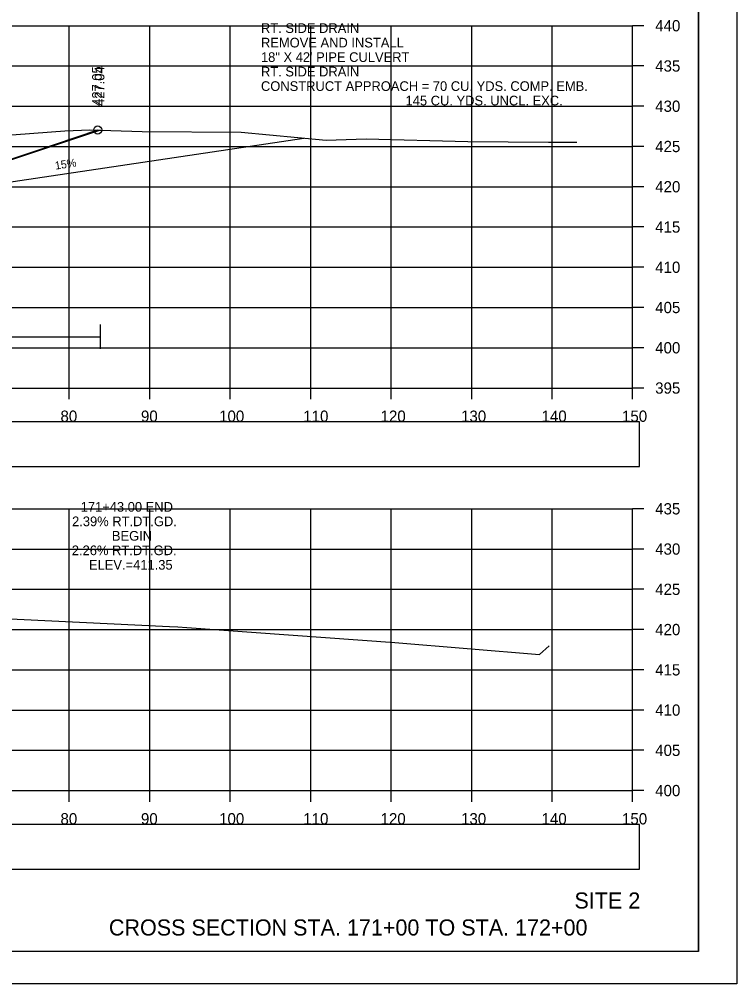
# Model space of a CAD drawing. Extents: x 1376273 to 1384221, y 378927 to 384592.
# Drawn here: x 1378664.4 to 1378753.6, y 381391.9 to 381511.6 of the extents above; entities that cross this region are included whole.
import ezdxf

# ---------------------------------------------------------------- set-up
doc = ezdxf.new("R2010")
doc.units = 0
for name, color, linetype in [('R_Axis', 7, 'Continuous'), ('R_Axis Annot', 7, 'Continuous'), ('R_Border', 7, 'Continuous'), ('R_Contours', 7, 'Continuous'), ('R_Dimension', 7, 'Continuous'), ('R_Draft', 7, 'Continuous'), ('R_Drive', 7, 'Continuous'), ('R_Exist Surface', 7, 'Continuous'), ('R_Fin Surface', 7, 'Continuous'), ('R_Grid', 7, 'Continuous'), ('R_No Plot', 7, 'Continuous'), ('R_Xsect Elev', 7, 'Continuous')]:
    doc.layers.add(name, color=color, linetype=linetype)

msp = doc.modelspace()

# ---------------------------------------------------------------- linework, layer by layer
at = {"layer": 'R_Axis'}
for p, q in [((1378740.64, 381465.85), (1378740.64, 381510.85)), ((1378742.04, 381510.85), (1378740.64, 381510.85)), ((1378742.04, 381505.85), (1378740.64, 381505.85)), ((1378742.04, 381500.85), (1378740.64, 381500.85)), ((1378742.04, 381495.85), (1378740.64, 381495.85)), ((1378742.04, 381490.85), (1378740.64, 381490.85)), ((1378742.04, 381485.85), (1378740.64, 381485.85)), ((1378742.04, 381480.85), (1378740.64, 381480.85)), ((1378742.04, 381475.85), (1378740.64, 381475.85)), ((1378742.04, 381470.85), (1378740.64, 381470.85)), ((1378440.64, 381465.85), (1378740.64, 381465.85)), ((1378670.64, 381464.45), (1378670.64, 381465.85)), ((1378680.64, 381464.45), (1378680.64, 381465.85)), ((1378690.64, 381464.45), (1378690.64, 381465.85)), ((1378700.64, 381464.45), (1378700.64, 381465.85)), ((1378710.64, 381464.45), (1378710.64, 381465.85)), ((1378720.64, 381464.45), (1378720.64, 381465.85)), ((1378730.64, 381464.45), (1378730.64, 381465.85)), ((1378740.64, 381464.45), (1378740.64, 381465.85)), ((1378742.04, 381465.85), (1378740.64, 381465.85)), ((1378740.64, 381415.85), (1378740.64, 381450.85)), ((1378742.04, 381450.85), (1378740.64, 381450.85)), ((1378742.04, 381445.85), (1378740.64, 381445.85)), ((1378742.04, 381440.85), (1378740.64, 381440.85)), ((1378742.04, 381435.85), (1378740.64, 381435.85)), ((1378742.04, 381430.85), (1378740.64, 381430.85)), ((1378742.04, 381425.85), (1378740.64, 381425.85)), ((1378742.04, 381420.85), (1378740.64, 381420.85)), ((1378440.64, 381415.85), (1378740.64, 381415.85)), ((1378670.64, 381414.45), (1378670.64, 381415.85)), ((1378680.64, 381414.45), (1378680.64, 381415.85)), ((1378690.64, 381414.45), (1378690.64, 381415.85)), ((1378700.64, 381414.45), (1378700.64, 381415.85)), ((1378710.64, 381414.45), (1378710.64, 381415.85)), ((1378720.64, 381414.45), (1378720.64, 381415.85)), ((1378730.64, 381414.45), (1378730.64, 381415.85)), ((1378740.64, 381414.45), (1378740.64, 381415.85)), ((1378742.04, 381415.85), (1378740.64, 381415.85))]:
    msp.add_line(p, q, dxfattribs=at)
at = {"layer": 'R_Axis Annot'}
for points in [[(1378439.67, 381456.11), (1378741.48, 381456.11), (1378741.48, 381461.64), (1378439.67, 381461.64)], [(1378439.67, 381406.1), (1378741.48, 381406.1), (1378741.48, 381411.63), (1378439.67, 381411.63)]]:
    msp.add_lwpolyline(points, close=True, dxfattribs=at)
at = {"layer": 'R_Border'}
for q in [(1378748.82, 381601.31), (1378432.64, 381395.85)]:
    msp.add_line((1378748.82, 381395.85), q, dxfattribs=at)
at = {"layer": 'R_Contours'}
msp.add_lwpolyline([(1378657.41, 381496.83), (1378670.1, 381497.8), (1378673.19, 381497.93), (1378674.51, 381497.89), (1378666.56, 381495.24), (1378631.54, 381483.55)], dxfattribs=at)
at = {"layer": 'R_Dimension'}
for p, q in [((1378674.51, 381470.72), (1378674.51, 381473.72)), ((1378556.18, 381472.22), (1378674.51, 381472.22))]:
    msp.add_line(p, q, dxfattribs=at)
at = {"layer": 'R_Drive'}
msp.add_line((1378643.52, 381488.52), (1378699.77, 381496.9), dxfattribs=at)
at = {"layer": 'R_Exist Surface'}
for points in [[(1378657.41, 381496.83), (1378670.1, 381497.8), (1378673.19, 381497.93), (1378679.7, 381497.72), (1378691.99, 381497.62), (1378702.55, 381496.64), (1378707.52, 381496.78), (1378720.17, 381496.47), (1378730.2, 381496.37), (1378733.71, 381496.38)], [(1378652.93, 381437.69), (1378683.11, 381436.23), (1378684.14, 381436.18), (1378685.23, 381436.11), (1378711.08, 381434.25), (1378729.08, 381432.77), (1378730.25, 381433.84)]]:
    msp.add_lwpolyline(points, dxfattribs=at)
at = {"layer": 'R_Fin Surface'}
msp.add_lwpolyline([(1378555.95, 381489.12), (1378556.64, 381488.89), (1378560.47, 381489.85), (1378566.64, 381491.39), (1378572.64, 381490.79), (1378590.64, 381488.99), (1378608.64, 381487.19), (1378614.64, 381486.59), (1378623.07, 381484.48), (1378624.64, 381484.09), (1378628.7, 381482.74), (1378631.21, 381483.56), (1378666.23, 381495.24), (1378674.18, 381497.9)], dxfattribs=at)
at = {"layer": 'R_Grid'}
for p, q in [((1378440.64, 381510.85), (1378740.64, 381510.85)), ((1378670.64, 381465.85), (1378670.64, 381510.85)), ((1378680.64, 381465.85), (1378680.64, 381510.85)), ((1378690.64, 381465.85), (1378690.64, 381510.85)), ((1378700.64, 381465.85), (1378700.64, 381510.85)), ((1378710.64, 381465.85), (1378710.64, 381510.85)), ((1378720.64, 381465.85), (1378720.64, 381510.85)), ((1378730.64, 381465.85), (1378730.64, 381510.85)), ((1378740.64, 381465.85), (1378740.64, 381510.85)), ((1378440.64, 381505.85), (1378740.64, 381505.85)), ((1378440.64, 381500.85), (1378740.64, 381500.85)), ((1378440.64, 381495.85), (1378740.64, 381495.85)), ((1378440.64, 381490.85), (1378740.64, 381490.85)), ((1378440.64, 381485.85), (1378740.64, 381485.85)), ((1378440.64, 381480.85), (1378740.64, 381480.85)), ((1378440.64, 381475.85), (1378740.64, 381475.85)), ((1378440.64, 381470.85), (1378740.64, 381470.85)), ((1378440.64, 381465.85), (1378740.64, 381465.85)), ((1378440.64, 381450.85), (1378740.64, 381450.85)), ((1378670.64, 381415.85), (1378670.64, 381450.85)), ((1378680.64, 381415.85), (1378680.64, 381450.85)), ((1378690.64, 381415.85), (1378690.64, 381450.85)), ((1378700.64, 381415.85), (1378700.64, 381450.85)), ((1378710.64, 381415.85), (1378710.64, 381450.85)), ((1378720.64, 381415.85), (1378720.64, 381450.85)), ((1378730.64, 381415.85), (1378730.64, 381450.85)), ((1378740.64, 381415.85), (1378740.64, 381450.85)), ((1378440.64, 381445.85), (1378740.64, 381445.85)), ((1378440.64, 381440.85), (1378740.64, 381440.85)), ((1378440.64, 381435.85), (1378740.64, 381435.85)), ((1378440.64, 381430.85), (1378740.64, 381430.85)), ((1378440.64, 381425.85), (1378740.64, 381425.85)), ((1378440.64, 381420.85), (1378740.64, 381420.85)), ((1378440.64, 381415.85), (1378740.64, 381415.85))]:
    msp.add_line(p, q, dxfattribs=at)
at = {"layer": 'R_No Plot'}
msp.add_line((1378420.24, 381391.87), (1378753.57, 381391.87), dxfattribs=at)
for points in [[(1378420.23, 381605.2), (1378753.57, 381605.2), (1378753.57, 381391.86), (1378420.23, 381391.86)], [(1378666.56, 381601.31), (1378666.56, 381591.43), (1378702.29, 381591.43), (1378702.29, 381588.51), (1378725.49, 381588.51), (1378725.49, 381564.17), (1378748.82, 381564.17), (1378748.82, 381395.85), (1378432.64, 381395.85), (1378432.64, 381601.31)]]:
    msp.add_lwpolyline(points, close=True, dxfattribs=at)
msp.add_circle((1378674.18, 381497.9), 0.5, dxfattribs=at)

# ---------------------------------------------------------------- texts
at = {"layer": 'R_Axis Annot'}
for s, height, p in [('RT. SIDE DRAIN', 1.2, (1378694.46, 381509.95)), ('440', 1.4, (1378743.44, 381510.15)), ('REMOVE AND INSTALL', 1.2, (1378694.46, 381508.15)), ('18" X 42\' PIPE CULVERT', 1.2, (1378694.46, 381506.35)), ('RT. SIDE DRAIN', 1.2, (1378694.46, 381504.55)), ('435', 1.4, (1378743.44, 381505.15)), ('CONSTRUCT APPROACH = 70 CU. YDS. COMP. EMB.', 1.2, (1378694.46, 381502.75)), ('        145 CU. YDS. UNCL. EXC.', 1.2, (1378708.86, 381500.95)), ('430', 1.4, (1378743.44, 381500.15)), ('425', 1.4, (1378743.44, 381495.15)), ('420', 1.4, (1378743.44, 381490.15)), ('415', 1.4, (1378743.44, 381485.15)), ('410', 1.4, (1378743.44, 381480.15)), ('405', 1.4, (1378743.44, 381475.15)), ('400', 1.4, (1378743.44, 381470.15)), ('395', 1.4, (1378743.44, 381465.15)), ('80', 1.4, (1378669.55, 381461.65)), ('90', 1.4, (1378679.55, 381461.65)), ('100', 1.4, (1378689.26, 381461.65)), ('110', 1.4, (1378699.72, 381461.65)), ('120', 1.4, (1378709.32, 381461.65)), ('130', 1.4, (1378719.32, 381461.65)), ('140', 1.4, (1378729.32, 381461.65)), ('150', 1.4, (1378739.32, 381461.65)), ('435', 1.4, (1378743.44, 381450.15)), ('430', 1.4, (1378743.44, 381445.15)), ('425', 1.4, (1378743.44, 381440.15)), ('420', 1.4, (1378743.44, 381435.15)), ('415', 1.4, (1378743.44, 381430.15)), ('410', 1.4, (1378743.44, 381425.15)), ('405', 1.4, (1378743.44, 381420.15)), ('400', 1.4, (1378743.44, 381415.15)), ('80', 1.4, (1378669.55, 381411.65)), ('90', 1.4, (1378679.55, 381411.65)), ('100', 1.4, (1378689.26, 381411.65)), ('110', 1.4, (1378699.72, 381411.65)), ('120', 1.4, (1378709.32, 381411.65)), ('130', 1.4, (1378719.32, 381411.65)), ('140', 1.4, (1378729.32, 381411.65)), ('150', 1.4, (1378739.32, 381411.65))]:
    msp.add_text(s, height=height, dxfattribs=at).set_placement(p)
at = {"layer": 'R_Draft'}
for s, p in [('SITE 2', (1378733.41, 381401.2)), ('CROSS SECTION STA. 171+00 TO STA. 172+00', (1378675.57, 381397.85))]:
    msp.add_text(s, height=2, dxfattribs=at).set_placement(p)
at = {"layer": 'R_Drive'}
msp.add_text('15%', height=1, rotation=8.531, dxfattribs=at).set_placement((1378668.93, 381492.97))
at = {"layer": 'R_No Plot'}
msp.add_text('427.04', height=1.2, rotation=90, dxfattribs=at).set_placement((1378675.01, 381500.89))
at = {"layer": 'R_Xsect Elev'}
for s, rotation, p in [('427.05', 90, (1378674.68, 381500.9)), ('171+43.00 END', 360, (1378672.06, 381450.49)), ('2.39% RT.DT.GD.', 360, (1378670.99, 381448.69)), ('BEGIN', 360, (1378675.94, 381446.89)), ('2.26% RT.DT.GD.', 360, (1378670.96, 381445.09)), ('ELEV.=411.35', 360, (1378673.09, 381443.29))]:
    msp.add_text(s, height=1.2, rotation=rotation, dxfattribs=at).set_placement(p)

doc.saveas('drawing.dxf')
